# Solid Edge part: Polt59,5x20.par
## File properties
Author: Türk
Template: Iso Part.par
Last saved by: Türk
Revision: 9
Application: Solid Edge
Accuracy: 0,990
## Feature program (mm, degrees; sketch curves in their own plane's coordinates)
thread "unnamed Thread 1"
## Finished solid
Body 1: solid body, 23 faces, 45 edges, 24 vertices.
  Faces by surface: plane 21, cylinder 2
  Edges by curve: line 42, circle 3
Bounding box of the edges (mm): 24.000 x 69.500 x 27.713, from (-12, -10, -13.8564) to (12, 59.5, 13.8564).
Cylindrical faces by radius (mm): R10 x2
Planar faces by outward normal: +x 1, +y 2, -x 1, -y 1, oblique 16
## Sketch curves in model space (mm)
circle centre (0, 0, 0) radius 13.8564
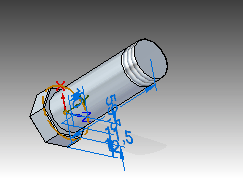
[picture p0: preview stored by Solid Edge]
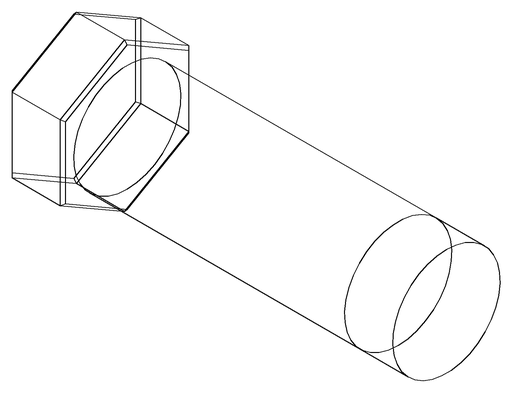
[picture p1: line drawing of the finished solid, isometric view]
